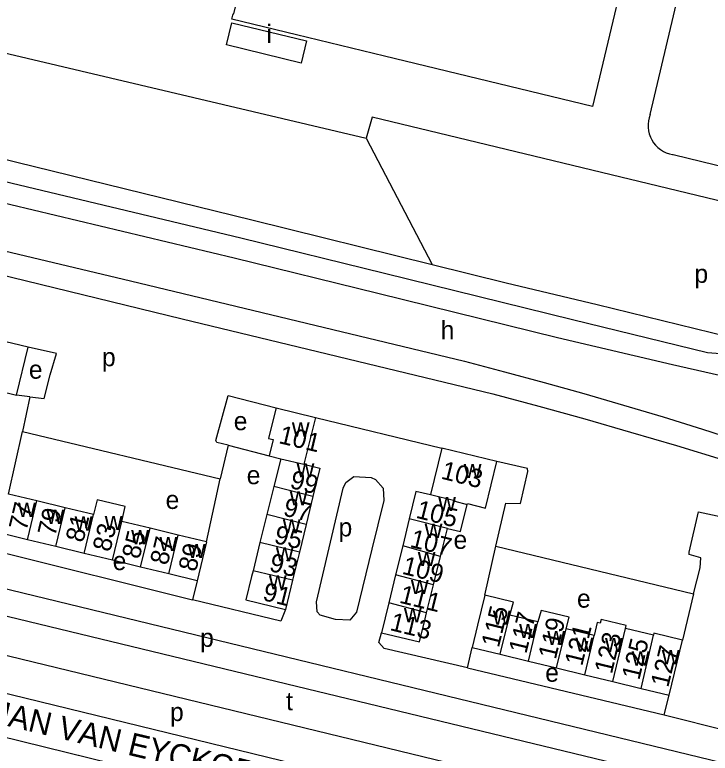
# Model space of a CAD drawing. Extents: x 162804 to 165059, y 381530 to 382901.
# Drawn here: x 163355.8 to 163507.1, y 382281.6 to 382442.3 of the extents above; entities that cross this region are included whole.
import ezdxf

# ---------------------------------------------------------------- set-up
doc = ezdxf.new("R2010")
doc.units = 0
for name, color, linetype in [('BLT_Basislijn', 7, 'Continuous'), ('BLT_Bebouwing', 7, 'Continuous'), ('BLT_Centroide', 7, 'Continuous'), ('BLT_Huisnummer', 7, 'Continuous'), ('BLT_Huisnummer_ tussenligend', 7, 'Continuous'), ('BLT_Onderverdeling_panden', 7, 'Continuous'), ('BLT_Straatnaam', 7, 'Continuous')]:
    doc.layers.add(name, color=color, linetype=linetype)

msp = doc.modelspace()

# ---------------------------------------------------------------- linework, layer by layer
at = {"layer": 'BLT_Basislijn'}
for p, q in [((163494.04, 382420.61), (163506.23, 382472.49)), ((163350, 382434.88), (163432.26, 382415.48)), ((163433.52, 382420.06), (163432.26, 382415.48)), ((163432.26, 382415.48), (163446.6, 382387.99)), ((163350, 382411.77), (163407.37, 382397.74)), ((163407.37, 382397.74), (163446.6, 382387.99)), ((163350, 382391.78), (163381.01, 382384.46)), ((163350, 382386.44), (163392.21, 382376.15)), ((163436.24, 382386.1), (163477.1, 382376.05)), ((163381.01, 382384.46), (163453.64, 382366.93)), ((163434.78, 382381.75), (163473.87, 382372.14)), ((163482.48, 382379.28), (163581.91, 382355.04)), ((163392.21, 382376.15), (163459.78, 382359.88)), ((163359.1, 382359.2), (163356.16, 382359.57)), ((163359.1, 382359.2), (163357.47, 382351.62)), ((163421.21, 382354.69), (163448.73, 382348.03)), ((163354.49, 382338.03), (163357.47, 382351.62)), ((163357.47, 382351.62), (163400.51, 382341.32)), ((163402.22, 382348.66), (163400.51, 382341.32)), ((163402.22, 382348.66), (163411.13, 382346.35)), ((163397.53, 382327.61), (163400.51, 382341.32)), ((163351.53, 382325.73), (163394.45, 382315.05)), ((163458.07, 382316.06), (163460.49, 382326.69)), ((163460.49, 382326.69), (163503.47, 382316.32)), ((163395.49, 382319.17), (163394.45, 382315.05)), ((163503.47, 382316.32), (163501.07, 382306.27)), ((163350, 382312.48), (163517.49, 382271.99)), ((163454.32, 382300.23), (163455.3, 382304.66)), ((163350, 382303.93), (163515.45, 382263.75)), ((163454.32, 382300.23), (163497.08, 382290.03)), ((163350, 382295.66), (163513.63, 382255.75)), ((163497.08, 382290.03), (163498.17, 382294.26)), ((163497.08, 382290.03), (163520.95, 382284.01))]:
    msp.add_line(p, q, dxfattribs=at)
for points in [[(163494.04, 382420.61), (163493.81, 382419.93), (163493.65, 382419.23), (163493.58, 382418.52), (163493.58, 382417.81), (163493.67, 382417.1), (163493.83, 382416.4), (163494.07, 382415.73), (163494.38, 382415.09), (163494.77, 382414.48), (163495.21, 382413.93), (163495.72, 382413.43), (163496.28, 382412.98), (163496.89, 382412.6), (163497.54, 382412.3), (163498.21, 382412.06), (163498.91, 382411.91), (163499.05, 382411.89)], [(163538.12, 382394.78), (163500, 382404.05), (163433.52, 382420.06)], [(163499.05, 382411.89), (163538.26, 382402.38)], [(163350, 382406.9), (163405.02, 382393.77), (163436.24, 382386.1)], [(163350, 382402.2), (163403.57, 382389.42), (163434.78, 382381.75)], [(163446.6, 382387.99), (163462.7, 382383.99), (163482.48, 382379.28)], [(163477.1, 382376.05), (163506.46, 382368.82), (163520.88, 382367.72), (163560.74, 382358)], [(163473.87, 382372.14), (163498.9, 382366.22), (163584.87, 382346.69)], [(163359.1, 382359.2), (163362.23, 382358.83), (163363.51, 382363.99), (163364.88, 382368.6), (163358.7, 382369.99)], [(163453.64, 382366.93), (163462.32, 382364.66), (163470.98, 382362.32), (163479.62, 382359.9), (163488.24, 382357.4), (163496.84, 382354.82), (163505.41, 382352.17), (163513.96, 382349.44), (163515.78, 382348.85)], [(163402.22, 382348.66), (163399.78, 382349.24), (163399.54, 382349.67), (163402.24, 382359.52), (163412.64, 382356.81)], [(163459.78, 382359.88), (163469.8, 382357.17), (163479.8, 382354.39), (163489.77, 382351.53), (163499.73, 382348.6), (163509.66, 382345.59), (163514.88, 382343.97)], [(163460.49, 382326.69), (163462.65, 382336.09), (163465.85, 382335.97), (163467.4, 382342.95), (163467.32, 382343.62), (163460.7, 382345.1)], [(163433.49, 382326.02), (163430.14, 382312.37), (163428.7, 382310.58), (163425.55, 382310.75), (163422.27, 382311.71), (163421.61, 382312.4), (163421.47, 382314.6), (163427.28, 382339.32), (163427.84, 382340.56), (163429.6, 382341.83), (163433.33, 382341.62), (163434.29, 382341.23), (163435.96, 382339.29), (163436.09, 382336.61), (163433.49, 382326.02)], [(163503.47, 382316.32), (163504.9, 382321.99), (163505.08, 382324.16), (163502.53, 382324.88), (163502.48, 382325.4), (163504.51, 382334.19), (163515.73, 382331.8)], [(163350, 382318.35), (163507.22, 382280.24), (163518.74, 382277.25)], [(163414.71, 382312.94), (163413.67, 382310.36), (163394.45, 382315.05)], [(163454.32, 382300.23), (163436.19, 382304.47), (163435.01, 382305.75), (163435.6, 382307.85)], [(163350, 382285.63), (163352.2, 382285.54), (163386.99, 382276.97), (163389.46, 382274.47), (163389.65, 382273.71), (163389.62, 382271.03), (163385.08, 382252.32), (163384.95, 382251.79)]]:
    msp.add_lwpolyline(points, dxfattribs=at)
at = {"layer": 'BLT_Bebouwing'}
for p, q in [((163401.86, 382435.8), (163403.02, 382440.56)), ((163403.02, 382440.56), (163419.26, 382436.63)), ((163419.26, 382436.63), (163418.1, 382431.82)), ((163418.1, 382431.82), (163401.86, 382435.8)), ((163358.7, 382369.99), (163350, 382372.1)), ((163351.87, 382360.61), (163356.16, 382359.57)), ((163412.64, 382356.81), (163421.21, 382354.69)), ((163421.21, 382354.69), (163418.7, 382344.53)), ((163448.73, 382348.03), (163446.25, 382337.95)), ((163460.7, 382345.1), (163448.73, 382348.03)), ((163411.13, 382346.35), (163413.66, 382345.72)), ((163413.66, 382345.72), (163412.17, 382339.68)), ((163412.17, 382339.68), (163410.66, 382333.58)), ((163360.64, 382336.54), (163354.49, 382338.03)), ((163420.67, 382337.48), (163419.2, 382331.43)), ((163366.79, 382335.05), (163360.64, 382336.54)), ((163372.93, 382333.56), (163366.79, 382335.05)), ((163410.66, 382333.58), (163409.15, 382327.47)), ((163385.24, 382330.59), (163379.08, 382332.08)), ((163441.63, 382332.67), (163440.2, 382326.79)), ((163391.38, 382329.1), (163385.24, 382330.59)), ((163419.2, 382331.43), (163417.73, 382325.38)), ((163448.41, 382324.42), (163449.92, 382330.54)), ((163358.59, 382328.1), (163352.44, 382329.58)), ((163397.53, 382327.61), (163391.38, 382329.1)), ((163364.74, 382326.61), (163358.59, 382328.1)), ((163409.15, 382327.47), (163407.64, 382321.37)), ((163370.89, 382325.12), (163364.74, 382326.61)), ((163440.2, 382326.79), (163438.66, 382320.46)), ((163377.04, 382323.63), (163370.89, 382325.12)), ((163417.73, 382325.38), (163416.26, 382319.33)), ((163446.91, 382318.3), (163448.41, 382324.42)), ((163383.19, 382322.15), (163377.04, 382323.63)), ((163389.34, 382320.66), (163383.19, 382322.15)), ((163395.49, 382319.17), (163389.34, 382320.66)), ((163416.26, 382319.33), (163414.71, 382312.94)), ((163438.66, 382320.46), (163437.18, 382314.34)), ((163445.41, 382312.18), (163446.91, 382318.3)), ((163437.18, 382314.34), (163435.6, 382307.85)), ((163469.62, 382310.21), (163463.49, 382311.69)), ((163481.87, 382307.24), (163475.74, 382308.72)), ((163494.76, 382307.31), (163488.66, 382308.81)), ((163455.3, 382304.66), (163461.43, 382303.17)), ((163461.43, 382303.17), (163467.55, 382301.69)), ((163467.55, 382301.69), (163473.67, 382300.2)), ((163473.67, 382300.2), (163479.8, 382298.71)), ((163479.8, 382298.71), (163485.92, 382297.23)), ((163485.92, 382297.23), (163492.05, 382295.74)), ((163492.05, 382295.74), (163498.17, 382294.26))]:
    msp.add_line(p, q, dxfattribs=at)
for points in [[(163403.02, 382441.4), (163403.32, 382442.56), (163403.49, 382442.52), (163405.5, 382450.85), (163404.25, 382451.15), (163406.27, 382459.52), (163407.55, 382459.21), (163410.25, 382470.48), (163405.27, 382471.71), (163408.19, 382483.84), (163413.21, 382482.6), (163416.88, 382499.12), (163364.14, 382511.89)], [(163506.23, 382472.49), (163500, 382474), (163494.11, 382475.43), (163484.1, 382433.33), (163481.49, 382422.35), (163436.24, 382433.33), (163417.07, 382437.99)], [(163417.07, 382437.99), (163403.02, 382441.4)], [(163356.16, 382359.57), (163358.7, 382369.99)], [(163412.64, 382356.81), (163411.44, 382351.96), (163410.99, 382350.13), (163412, 382349.88), (163411.13, 382346.35)], [(163454.23, 382335.8), (163454.27, 382335.96), (163458.22, 382334.99), (163460.7, 382345.1)], [(163418.7, 382344.53), (163422.17, 382343.68), (163420.67, 382337.48)], [(163446.25, 382337.95), (163446.23, 382337.86), (163443.08, 382338.62), (163441.63, 382332.67)], [(163379.08, 382332.08), (163379.85, 382335.31), (163373.74, 382336.79), (163372.93, 382333.56)], [(163449.92, 382330.54), (163452.79, 382329.93), (163454.23, 382335.8)], [(163397.53, 382327.61), (163396.66, 382324.03), (163395.49, 382319.17)], [(163407.64, 382321.37), (163407.33, 382320.13), (163406.07, 382315.01), (163414.71, 382312.94)], [(163458.07, 382316.06), (163456.48, 382309.52), (163455.3, 382304.66)], [(163463.49, 382311.69), (163464.31, 382314.55), (163458.07, 382316.06)], [(163475.74, 382308.72), (163476.37, 382311.23), (163470.29, 382312.7), (163469.62, 382310.21)], [(163435.6, 382307.85), (163443.86, 382305.86), (163445.1, 382310.91), (163445.41, 382312.18)], [(163488.66, 382308.81), (163488.81, 382309.42), (163483.37, 382310.74), (163483.17, 382309.94), (163482.53, 382310.09), (163481.87, 382307.24)], [(163501.07, 382306.27), (163494.85, 382307.77), (163494.76, 382307.31)], [(163498.17, 382294.26), (163501.07, 382306.27)]]:
    msp.add_lwpolyline(points, dxfattribs=at)
at = {"layer": 'BLT_Onderverdeling_panden'}
for p, q in [((163413.66, 382345.72), (163418.7, 382344.53)), ((163420.67, 382337.48), (163412.17, 382339.68)), ((163358.59, 382328.1), (163360.64, 382336.54)), ((163364.74, 382326.61), (163366.79, 382335.05)), ((163370.89, 382325.12), (163372.93, 382333.56)), ((163419.2, 382331.43), (163410.66, 382333.58)), ((163377.04, 382323.63), (163379.08, 382332.08)), ((163449.92, 382330.54), (163441.63, 382332.67)), ((163383.19, 382322.15), (163385.24, 382330.59)), ((163389.34, 382320.66), (163391.38, 382329.1)), ((163417.73, 382325.38), (163409.15, 382327.47)), ((163448.41, 382324.42), (163440.2, 382326.79)), ((163416.26, 382319.33), (163407.64, 382321.37)), ((163446.91, 382318.3), (163438.66, 382320.46)), ((163445.41, 382312.18), (163437.18, 382314.34)), ((163461.43, 382303.17), (163463.49, 382311.69)), ((163467.55, 382301.69), (163469.62, 382310.21)), ((163473.67, 382300.2), (163475.74, 382308.72)), ((163485.92, 382297.23), (163488.66, 382308.81)), ((163479.8, 382298.71), (163481.87, 382307.24)), ((163492.05, 382295.74), (163494.76, 382307.31))]:
    msp.add_line(p, q, dxfattribs=at)
msp.add_lwpolyline([(163446.25, 382337.95), (163451.57, 382336.64), (163451.53, 382336.47), (163454.23, 382335.8)], dxfattribs=at)

# ---------------------------------------------------------------- texts
at = {"layer": 'BLT_Centroide'}
for s, p in [('i', (163410.55, 382436.19)), ('p', (163503.66, 382383.99)), ('h', (163448.45, 382371.73)), ('p', (163374.79, 382365.85)), ('e', (163358.89, 382363.14)), ('e', (163403.45, 382351.94)), ('w', (163416.09, 382350.56)), ('w', (163417.12, 382341.66)), ('e', (163406.27, 382340.18)), ('w', (163453.47, 382341.5)), ('w', (163415.62, 382335.59)), ('e', (163388.63, 382334.8)), ('w', (163447.91, 382334.34)), ('w', (163356.53, 382333.06)), ('w', (163362.69, 382331.56)), ('w', (163368.84, 382330.09)), ('w', (163375.38, 382330.22)), ('w', (163414.11, 382329.47)), ('p', (163426.25, 382328.83)), ('w', (163444.97, 382328.5)), ('w', (163381.14, 382327.12)), ('w', (163387.28, 382325.62)), ('e', (163451.26, 382326.11)), ('w', (163393.44, 382324.12)), ('w', (163412.61, 382323.38)), ('w', (163443.47, 382322.38)), ('e', (163377.12, 382321.5)), ('w', (163411.09, 382317.28)), ('w', (163441.97, 382316.28)), ('e', (163478.11, 382313.32)), ('w', (163440.46, 382310.16)), ('w', (163459.8, 382309.59)), ('w', (163465.52, 382306.69)), ('p', (163396.14, 382304.79)), ('w', (163471.64, 382305.2)), ('w', (163477.77, 382303.72)), ('w', (163484.2, 382303.67)), ('w', (163490.02, 382300.73)), ('w', (163496.56, 382301.02)), ('e', (163471.2, 382297.2)), ('t', (163414.84, 382290.99)), ('p', (163389.59, 382288.65))]:
    msp.add_text(s, height=4, dxfattribs=at).set_placement(p)
at = {"layer": 'BLT_Huisnummer'}
for s, rotation, p in [('101', 346.7291, (163413.04, 382349.15)), ('103', 345.9272, (163448.35, 382341.43)), ('99', 346.1047, (163415.47, 382339.4)), ('77', 76.4021, (163358.34, 382329.87)), ('105', 345.9272, (163442.9, 382332.92)), ('81', 76.4021, (163370.69, 382327.33)), ('95', 346.1047, (163412.02, 382327.43)), ('85', 76.4006, (163382.93, 382323.73)), ('89', 76.4, (163395.22, 382320.97)), ('109', 346.2194, (163439.87, 382320.72)), ('91', 346.1032, (163409.54, 382315.01)), ('115', 76.3584, (163461.1, 382304.47)), ('113', 346.2194, (163437.21, 382308.47)), ('119', 76.3568, (163473.48, 382301.91)), ('123', 76.3568, (163485.68, 382298.73)), ('127', 76.3416, (163497.94, 382295.81))]:
    msp.add_text(s, height=4, rotation=rotation, dxfattribs=at).set_placement(p)
at = {"layer": 'BLT_Huisnummer_ tussenligend'}
for s, rotation, p in [('97', 346.1047, (163414, 382333.42)), ('79', 76.4021, (163364.59, 382328.68)), ('83', 76.4021, (163376.56, 382325.3)), ('87', 76.4006, (163389.04, 382322.39)), ('107', 346.2194, (163441.59, 382326.57)), ('93', 346.1032, (163410.96, 382321.36)), ('111', 346.2194, (163439.27, 382314.43)), ('117', 76.3584, (163467.07, 382303.13)), ('121', 76.3568, (163479.23, 382300.48)), ('125', 76.3568, (163491.65, 382297.4))]:
    msp.add_text(s, height=4, rotation=rotation, dxfattribs=at).set_placement(p)
at = {"layer": 'BLT_Straatnaam'}
msp.add_text('JAN VAN EYCKGRACHT', height=4.9999, rotation=346.5464, dxfattribs=at).set_placement((163350.88, 382288.36))

doc.saveas('drawing.dxf')
